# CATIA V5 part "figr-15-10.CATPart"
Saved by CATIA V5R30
Part number: Part1
Bounding box of the stored display mesh (mm): x -50 to 50, y -32.5 to 33.5, z -52 to 1
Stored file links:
  D:\PROJECTS\CATIA V56R 2020\Resources\Parts File\c15_catia_v5_6r2020_prt\figr-15-10.CATPart
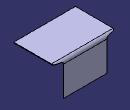
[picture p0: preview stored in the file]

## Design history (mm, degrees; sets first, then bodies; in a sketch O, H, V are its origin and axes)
SheetMetalParameters1: Thickness 1, BendRadius 4, KFactor 0.475772 {= log(min(100,max(20*SheetMetalParameters1.BendRadius,SheetMetalParameters1.Thickness)/SheetMetalParameters1.Thickness))/log(100)/2}, ReliefRadialLength 4, ReliefAxialLength 4, MinimumBendRadius 0
Body1 (main body)
  Sketch1 on xy-plane, origin (0, 0, 0), H (1, 0, 0), V (0, 1, 0)
    line L1 (-50, 32.5) -> (50, 32.5)
    line L2 (50, 32.5) -> (50, -32.5)
    line L3 (50, -32.5) -> (-50, -32.5)
    line L4 (-50, -32.5) -> (-50, 32.5)
    length L1 = 100
    length L2 = 65
    horizontal: L1 H, L3 H
    vertical: L2 V, L4 V
    symmetry: L4 L2 V, L1 L3 H
  Wall1: Thickness 1, Profile Sketch1
  d_NewWallOnEdge1: NewWallOnEdge_Edge edge [face of Wall1 | face of Wall1], NewWallOnEdge_Length 53, NewWallOnEdge_HeightLimitOffset 0, NewWallOnEdge_WidthOffset1 -15, NewWallOnEdge_WidthOffset2 -15, NewWallOnEdge_Angle 90, NewWallOnEdge_BendRadiusValue 4 {= SheetMetalParameters1.BendRadius}, NewWallOnEdge_BendTable SheetMetalParameters1, KFacteur 0.475772 {= log(min(100,max(20*d_NewWallOnEdge1.Radius,SheetMetalParameters1.Thickness)/SheetMetalParameters1.Thickness))/log(100)/2}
